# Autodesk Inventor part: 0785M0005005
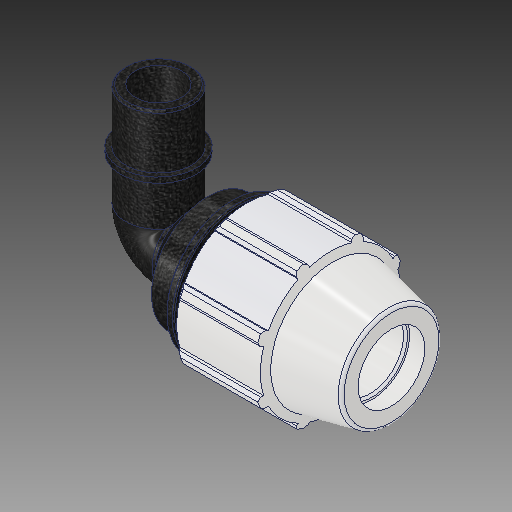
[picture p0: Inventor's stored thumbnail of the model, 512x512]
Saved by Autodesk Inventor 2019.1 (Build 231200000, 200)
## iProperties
Created: 2017-02
Part Number: 0785M0005005
Material: PVC-Piping
Description: PLASSON 90° ELBOW MALE ADAPTOR 1/2''-1/2''M
Document SubType Name: Modeling
Designer: KIM
Mass: 92.6774 g
Surface Area: 199.44 cm^2
Volume: 66.1981 cm^3
Density: 1.4 g/cm^3
Appearance: PTFE
Author: KIM
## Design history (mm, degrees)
derived "0785M0.ipt"
feature "Solid1::0785M0.ipt"
tag "TaggingFeature1"
body "Solid1"
other parameters: "d2" = 21.2, "d4" = 6.1595, "d5" = 18.4785, "d7" = 48.006, "d9" = 10.55914, "d11" = 2.4638, "d13" = 120 deg, "d14" = 31.8, "d15" = 12 deg, "d16" = 41.76522, "d18" = 1.06, "d19" = 35 deg, "d20" = 17.5 deg, "d21" = 44.64558, "d23" = 0, "d25" = 360 deg, "d27" = 0.96012, "d33" = 0.424, "d42" = 27.34818, "d43" = 1.44018, "d46" = 0.636, "d51" = 73.914, "d68" = 2.4638, "d72" = 40.894, "d73" = 20.955, "d74" = 17.018, "d75" = 24.09825, "d76" = 14.6685, "d77" = 18.7198, "d79" = 8.382, "d80" = 0.62865, "d83" = 0, "d84" = 0, "d91" = 36.0045, "d93" = 56.896, "d94" = 20.955, "d95" = 14.6685, "d96" = 7.3914, "d97" = 50 deg, "d_" = 21.2, "E_" = 48.006, "A_" = 73.914, "l_" = 56.896, "l_2" = 17.018, "A_1" = 40.894, "G_" = 20.955
